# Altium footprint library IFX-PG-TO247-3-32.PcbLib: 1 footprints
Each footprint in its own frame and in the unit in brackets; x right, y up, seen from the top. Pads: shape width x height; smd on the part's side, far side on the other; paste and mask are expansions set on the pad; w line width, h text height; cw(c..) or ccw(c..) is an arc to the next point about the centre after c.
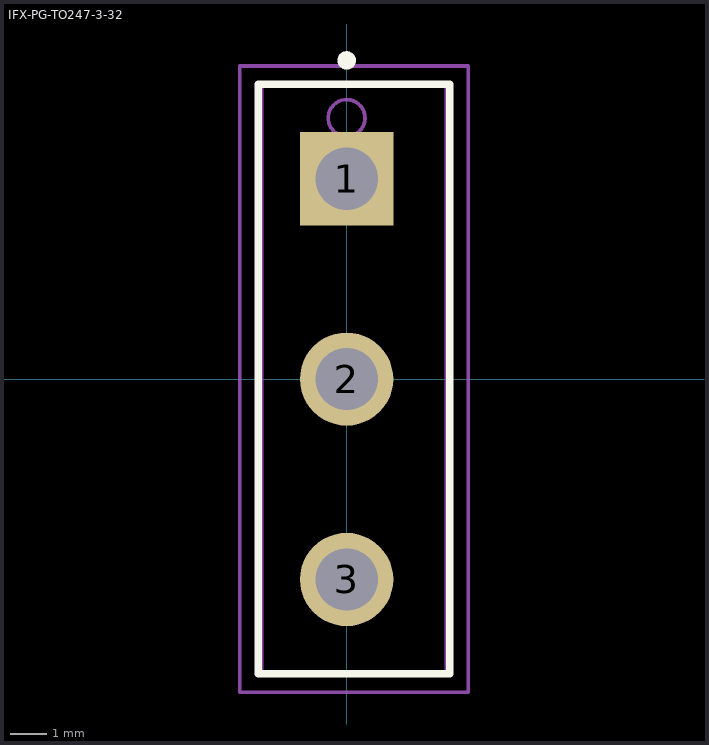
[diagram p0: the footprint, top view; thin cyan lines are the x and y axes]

## IFX-PG-TO247-3-32 [mm] "TO-247-3; 5.44mm pitch, 3 pin, 15.915 mm L X 5.02 mm W X 26.20 mm H body"
height 26.2
pads (3):
  rect 2.535x2.535 hole 1.69 paste+0 mask+0: 1(0,5.44)
  round 2.535 hole 1.69 paste+0 mask+0: 2(0,0) 3(0,-5.44)
Top Overlay:
  circle w0.25: c0,8.65 r0.125
  lines w0.2: -2.4,-8 2.8,-8 2.8,8 -2.4,8 -2.4,-8
M3 (ASY_Text_Top):
  text ".DESIGNATOR" at 0,0 h1.2
M13 (CMP_Body_OTL_Top):
  circle w0.1: c0,7.087 r0.5
  lines w0.1: -2.308,-7.957 -2.308,7.957 2.712,7.957 2.712,-7.957 -2.308,-7.957
M15 (CMP_Courtyard_Top):
  lines w0.1: -0.5,0 0.5,0 ; 0,-0.5 0,0.5 ; -2.9,-8.5 -2.9,8.5 3.3,8.5 3.3,-8.5 -2.9,-8.5
3D body "PG-TO247-3-32.STEP": height 26.2, standoff -14.96, extent -2.307,-7.957 2.713,7.957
